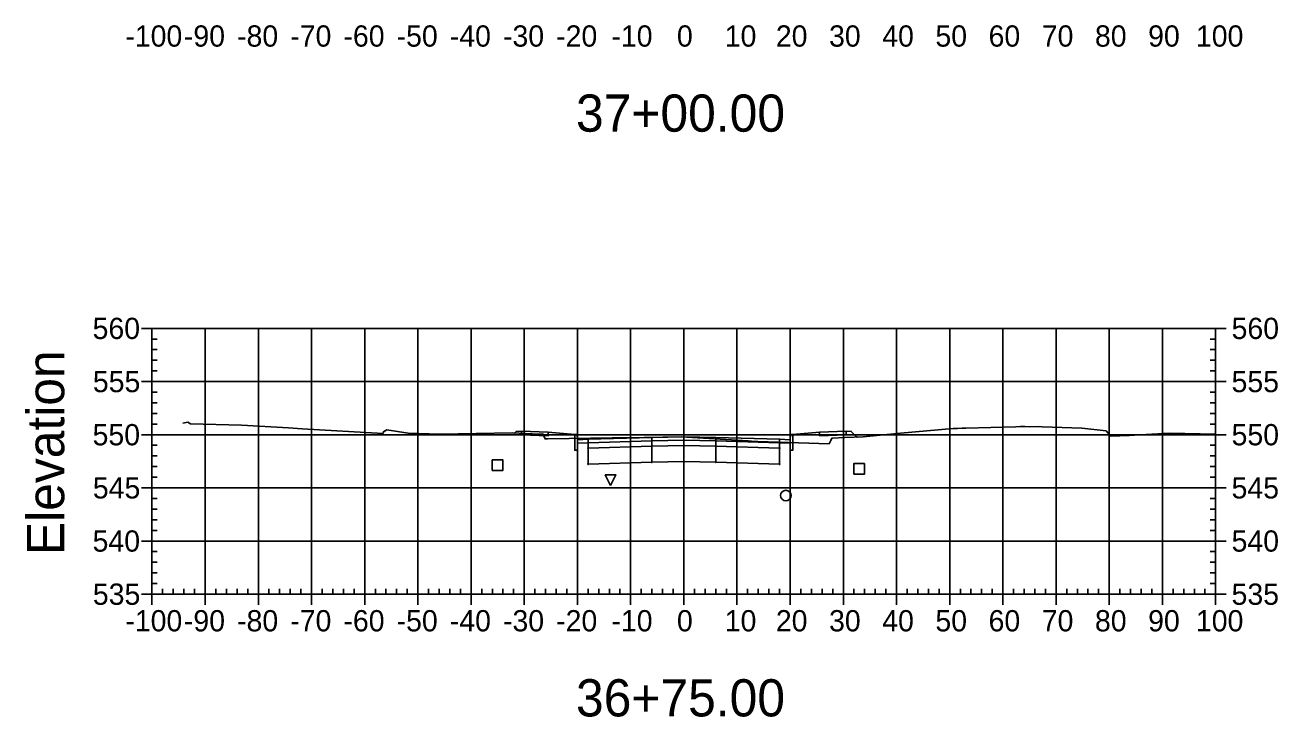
# Model space of a CAD drawing. Extents: x 704834 to 709892, y 372981 to 377533.
# Drawn here: x 709381 to 709616.6, y 376017.7 to 376147.9 of the extents above; entities that cross this region are included whole.
import ezdxf

# ---------------------------------------------------------------- set-up
doc = ezdxf.new("R2010")
doc.units = 0
for name, color, linetype in [('1', 7, 'Continuous'), ('10', 7, 'Continuous'), ('13', 7, 'Continuous'), ('14', 7, 'Continuous'), ('4', 7, 'Continuous'), ('57', 7, 'Continuous'), ('60', 7, 'Continuous'), ('Default_Xsect', 7, 'Continuous'), ('Existing', 7, 'Continuous')]:
    doc.layers.add(name, color=color, linetype=linetype)

msp = doc.modelspace()

# ---------------------------------------------------------------- linework, layer by layer
for points in [[(709473.41, 376071.44), (709473.1, 376071.12)], [(709474.41, 376071.48), (709473.41, 376071.44)], [(709484.41, 376070.88), (709479.41, 376071.28)], [(709525.41, 376070.88), (709530.41, 376071.28)], [(709535.41, 376071.48), (709536.41, 376071.44)], [(709536.41, 376071.44), (709537.47, 376070.38)]]:
    msp.add_lwpolyline(points)
for points in [[(709479.41, 376071.28), (709474.41, 376071.48), (709474.41, 376070.81), (709479.41, 376070.61)], [(709484.91, 376069.88), (709484.83, 376070.88), (709484.41, 376070.88), (709484.41, 376067.88), (709484.91, 376067.88)], [(709486.91, 376069.96), (709484.91, 376069.88), (709484.91, 376069.21), (709486.91, 376069.29)], [(709498.91, 376070.32), (709486.91, 376069.96), (709486.91, 376069.29), (709498.91, 376069.65)], [(709498.91, 376069.65), (709486.91, 376069.29), (709486.91, 376068.29), (709498.91, 376068.65)], [(709498.86, 376069.6), (709498.96, 376069.6), (709498.96, 376069.7), (709498.86, 376069.7)], [(709504.91, 376070.44), (709498.91, 376070.32), (709498.91, 376069.65), (709504.91, 376069.77)], [(709504.91, 376069.77), (709498.91, 376069.65), (709498.91, 376068.65), (709504.91, 376068.77)], [(709504.86, 376069.72), (709504.96, 376069.72), (709504.96, 376069.82), (709504.86, 376069.82)], [(709504.91, 376069.77), (709510.91, 376069.65), (709510.91, 376070.32), (709504.91, 376070.44)], [(709504.91, 376068.77), (709510.91, 376068.65), (709510.91, 376069.65), (709504.91, 376069.77)], [(709510.86, 376069.6), (709510.96, 376069.6), (709510.96, 376069.7), (709510.86, 376069.7)], [(709510.91, 376069.65), (709522.91, 376069.29), (709522.91, 376069.96), (709510.91, 376070.32)], [(709510.91, 376068.65), (709522.91, 376068.29), (709522.91, 376069.29), (709510.91, 376069.65)], [(709522.91, 376069.29), (709524.91, 376069.21), (709524.91, 376069.88), (709522.91, 376069.96)], [(709524.91, 376067.88), (709525.41, 376067.88), (709525.41, 376070.88), (709525, 376070.88), (709524.91, 376069.88)], [(709530.41, 376070.61), (709535.41, 376070.81), (709535.41, 376071.48), (709530.41, 376071.28)], [(709486.86, 376068.24), (709486.96, 376068.24), (709486.96, 376068.34), (709486.86, 376068.34)], [(709498.91, 376068.65), (709486.91, 376068.29), (709486.91, 376065.29), (709498.91, 376065.65)], [(709498.86, 376068.6), (709498.96, 376068.6), (709498.96, 376068.7), (709498.86, 376068.7)], [(709504.91, 376068.77), (709498.91, 376068.65), (709498.91, 376065.65), (709504.91, 376065.77)], [(709504.86, 376068.72), (709504.96, 376068.72), (709504.96, 376068.82), (709504.86, 376068.82)], [(709504.91, 376065.77), (709510.91, 376065.65), (709510.91, 376068.65), (709504.91, 376068.77)], [(709510.86, 376068.6), (709510.96, 376068.6), (709510.96, 376068.7), (709510.86, 376068.7)], [(709510.91, 376065.65), (709522.91, 376065.29), (709522.91, 376068.29), (709510.91, 376068.65)], [(709522.86, 376068.24), (709522.96, 376068.24), (709522.96, 376068.34), (709522.86, 376068.34)], [(709486.86, 376065.24), (709486.96, 376065.24), (709486.96, 376065.34), (709486.86, 376065.34)], [(709498.86, 376065.6), (709498.96, 376065.6), (709498.96, 376065.7), (709498.86, 376065.7)], [(709504.86, 376065.72), (709504.96, 376065.72), (709504.96, 376065.82), (709504.86, 376065.82)], [(709510.86, 376065.6), (709510.96, 376065.6), (709510.96, 376065.7), (709510.86, 376065.7)], [(709522.86, 376065.24), (709522.96, 376065.24), (709522.96, 376065.34), (709522.86, 376065.34)]]:
    msp.add_lwpolyline(points, close=True)
at = {"layer": '1'}
msp.add_lwpolyline([(709491.13, 376061.24), (709490.13, 376063.24), (709492.13, 376063.24)], close=True, dxfattribs=at)
at = {"layer": '10'}
msp.add_lwpolyline([(709468.89, 376064.09), (709470.89, 376064.09), (709470.89, 376066.09), (709468.89, 376066.09)], close=True, dxfattribs=at)
at = {"layer": '13'}
msp.add_circle((709524.1, 376059.37), 1, dxfattribs=at)
at = {"layer": '14'}
for points in [[(709473.1, 376071.12), (709473.1, 376071.17), (709473.1, 376071.12), (709473.05, 376071.12), (709473.1, 376071.12), (709473.1, 376071.07), (709473.1, 376071.12), (709473.15, 376071.12)], [(709486.91, 376069.96), (709486.91, 376070.01), (709486.91, 376069.96), (709486.86, 376069.96), (709486.91, 376069.96), (709486.91, 376069.91), (709486.91, 376069.96), (709486.96, 376069.96)], [(709504.91, 376070.44), (709504.91, 376070.49), (709504.91, 376070.44), (709504.86, 376070.44), (709504.91, 376070.44), (709504.91, 376070.39), (709504.91, 376070.44), (709504.96, 376070.44)], [(709522.91, 376069.96), (709522.91, 376070.01), (709522.91, 376069.96), (709522.86, 376069.96), (709522.91, 376069.96), (709522.91, 376069.91), (709522.91, 376069.96), (709522.96, 376069.96)], [(709537.47, 376070.38), (709537.47, 376070.43), (709537.47, 376070.38), (709537.42, 376070.38), (709537.47, 376070.38), (709537.47, 376070.33), (709537.47, 376070.38), (709537.52, 376070.38)]]:
    msp.add_lwpolyline(points, dxfattribs=at)
at = {"layer": '4'}
msp.add_lwpolyline([(709536.88, 376063.39), (709538.88, 376063.39), (709538.88, 376065.39), (709536.88, 376065.39)], close=True, dxfattribs=at)
at = {"layer": '57'}
for p, q in [((709402.91, 376090.82), (709404.91, 376090.82)), ((709404.91, 376090.82), (709604.91, 376090.82)), ((709404.91, 376040.82), (709404.91, 376090.82)), ((709404.91, 376040.82), (709404.91, 376090.82)), ((709414.91, 376040.82), (709414.91, 376090.82)), ((709424.91, 376040.82), (709424.91, 376090.82)), ((709434.91, 376040.82), (709434.91, 376090.82)), ((709444.91, 376040.82), (709444.91, 376090.82)), ((709454.91, 376040.82), (709454.91, 376090.82)), ((709464.91, 376040.82), (709464.91, 376090.82)), ((709474.91, 376040.82), (709474.91, 376090.82)), ((709484.91, 376040.82), (709484.91, 376090.82)), ((709494.91, 376040.82), (709494.91, 376090.82)), ((709504.91, 376040.82), (709504.91, 376090.82)), ((709514.91, 376040.82), (709514.91, 376090.82)), ((709524.91, 376040.82), (709524.91, 376090.82)), ((709534.91, 376040.82), (709534.91, 376090.82)), ((709544.91, 376040.82), (709544.91, 376090.82)), ((709554.91, 376040.82), (709554.91, 376090.82)), ((709564.91, 376040.82), (709564.91, 376090.82)), ((709574.91, 376040.82), (709574.91, 376090.82)), ((709584.91, 376040.82), (709584.91, 376090.82)), ((709594.91, 376040.82), (709594.91, 376090.82)), ((709604.91, 376040.82), (709604.91, 376090.82)), ((709604.91, 376040.82), (709604.91, 376090.82)), ((709606.91, 376090.82), (709604.91, 376090.82)), ((709404.91, 376088.82), (709405.91, 376088.82)), ((709604.91, 376088.82), (709603.91, 376088.82)), ((709404.91, 376086.82), (709405.91, 376086.82)), ((709604.91, 376086.82), (709603.91, 376086.82)), ((709404.91, 376084.82), (709405.91, 376084.82)), ((709604.91, 376084.82), (709603.91, 376084.82)), ((709404.91, 376082.82), (709405.91, 376082.82)), ((709604.91, 376082.82), (709603.91, 376082.82)), ((709402.91, 376080.82), (709404.91, 376080.82)), ((709404.91, 376080.82), (709604.91, 376080.82)), ((709404.91, 376078.82), (709405.91, 376078.82)), ((709604.91, 376078.82), (709603.91, 376078.82)), ((709606.91, 376080.82), (709604.91, 376080.82)), ((709404.91, 376076.82), (709405.91, 376076.82)), ((709604.91, 376076.82), (709603.91, 376076.82)), ((709404.91, 376074.82), (709405.91, 376074.82)), ((709604.91, 376074.82), (709603.91, 376074.82)), ((709404.91, 376072.82), (709405.91, 376072.82)), ((709604.91, 376072.82), (709603.91, 376072.82)), ((709402.91, 376070.82), (709404.91, 376070.82)), ((709404.91, 376070.82), (709604.91, 376070.82)), ((709606.91, 376070.82), (709604.91, 376070.82)), ((709404.91, 376068.82), (709405.91, 376068.82)), ((709604.91, 376068.82), (709603.91, 376068.82)), ((709404.91, 376066.82), (709405.91, 376066.82)), ((709404.91, 376064.82), (709405.91, 376064.82)), ((709604.91, 376066.82), (709603.91, 376066.82)), ((709604.91, 376064.82), (709603.91, 376064.82)), ((709404.91, 376062.82), (709405.91, 376062.82)), ((709604.91, 376062.82), (709603.91, 376062.82)), ((709402.91, 376060.82), (709404.91, 376060.82)), ((709404.91, 376060.82), (709604.91, 376060.82)), ((709606.91, 376060.82), (709604.91, 376060.82)), ((709404.91, 376058.82), (709405.91, 376058.82)), ((709604.91, 376058.82), (709603.91, 376058.82)), ((709404.91, 376056.82), (709405.91, 376056.82)), ((709604.91, 376056.82), (709603.91, 376056.82)), ((709404.91, 376054.82), (709405.91, 376054.82)), ((709604.91, 376054.82), (709603.91, 376054.82)), ((709402.91, 376050.82), (709404.91, 376050.82)), ((709404.91, 376052.82), (709405.91, 376052.82)), ((709404.91, 376050.82), (709604.91, 376050.82)), ((709604.91, 376052.82), (709603.91, 376052.82)), ((709606.91, 376050.82), (709604.91, 376050.82)), ((709404.91, 376048.82), (709405.91, 376048.82)), ((709604.91, 376048.82), (709603.91, 376048.82)), ((709404.91, 376046.82), (709405.91, 376046.82)), ((709604.91, 376046.82), (709603.91, 376046.82)), ((709404.91, 376044.82), (709405.91, 376044.82)), ((709604.91, 376044.82), (709603.91, 376044.82)), ((709404.91, 376042.82), (709405.91, 376042.82)), ((709406.91, 376040.82), (709406.91, 376041.82)), ((709408.91, 376040.82), (709408.91, 376041.82)), ((709410.91, 376040.82), (709410.91, 376041.82)), ((709412.91, 376040.82), (709412.91, 376041.82)), ((709416.91, 376040.82), (709416.91, 376041.82)), ((709418.91, 376040.82), (709418.91, 376041.82)), ((709420.91, 376040.82), (709420.91, 376041.82)), ((709422.91, 376040.82), (709422.91, 376041.82)), ((709426.91, 376040.82), (709426.91, 376041.82)), ((709428.91, 376040.82), (709428.91, 376041.82)), ((709430.91, 376040.82), (709430.91, 376041.82)), ((709432.91, 376040.82), (709432.91, 376041.82)), ((709436.91, 376040.82), (709436.91, 376041.82)), ((709438.91, 376040.82), (709438.91, 376041.82)), ((709440.91, 376040.82), (709440.91, 376041.82)), ((709442.91, 376040.82), (709442.91, 376041.82)), ((709446.91, 376040.82), (709446.91, 376041.82)), ((709448.91, 376040.82), (709448.91, 376041.82)), ((709450.91, 376040.82), (709450.91, 376041.82)), ((709452.91, 376040.82), (709452.91, 376041.82)), ((709456.91, 376040.82), (709456.91, 376041.82)), ((709458.91, 376040.82), (709458.91, 376041.82)), ((709460.91, 376040.82), (709460.91, 376041.82)), ((709462.91, 376040.82), (709462.91, 376041.82)), ((709466.91, 376040.82), (709466.91, 376041.82)), ((709468.91, 376040.82), (709468.91, 376041.82)), ((709470.91, 376040.82), (709470.91, 376041.82)), ((709472.91, 376040.82), (709472.91, 376041.82)), ((709476.91, 376040.82), (709476.91, 376041.82)), ((709478.91, 376040.82), (709478.91, 376041.82)), ((709480.91, 376040.82), (709480.91, 376041.82)), ((709482.91, 376040.82), (709482.91, 376041.82)), ((709486.91, 376040.82), (709486.91, 376041.82)), ((709488.91, 376040.82), (709488.91, 376041.82)), ((709490.91, 376040.82), (709490.91, 376041.82)), ((709492.91, 376040.82), (709492.91, 376041.82)), ((709496.91, 376040.82), (709496.91, 376041.82)), ((709498.91, 376040.82), (709498.91, 376041.82)), ((709500.91, 376040.82), (709500.91, 376041.82)), ((709502.91, 376040.82), (709502.91, 376041.82)), ((709506.91, 376040.82), (709506.91, 376041.82)), ((709508.91, 376040.82), (709508.91, 376041.82)), ((709510.91, 376040.82), (709510.91, 376041.82)), ((709512.91, 376040.82), (709512.91, 376041.82)), ((709516.91, 376040.82), (709516.91, 376041.82)), ((709518.91, 376040.82), (709518.91, 376041.82)), ((709520.91, 376040.82), (709520.91, 376041.82)), ((709522.91, 376040.82), (709522.91, 376041.82)), ((709526.91, 376040.82), (709526.91, 376041.82)), ((709528.91, 376040.82), (709528.91, 376041.82)), ((709530.91, 376040.82), (709530.91, 376041.82)), ((709532.91, 376040.82), (709532.91, 376041.82)), ((709536.91, 376040.82), (709536.91, 376041.82)), ((709538.91, 376040.82), (709538.91, 376041.82)), ((709540.91, 376040.82), (709540.91, 376041.82)), ((709542.91, 376040.82), (709542.91, 376041.82)), ((709546.91, 376040.82), (709546.91, 376041.82)), ((709548.91, 376040.82), (709548.91, 376041.82)), ((709550.91, 376040.82), (709550.91, 376041.82)), ((709552.91, 376040.82), (709552.91, 376041.82)), ((709556.91, 376040.82), (709556.91, 376041.82)), ((709558.91, 376040.82), (709558.91, 376041.82)), ((709560.91, 376040.82), (709560.91, 376041.82)), ((709562.91, 376040.82), (709562.91, 376041.82)), ((709566.91, 376040.82), (709566.91, 376041.82)), ((709568.91, 376040.82), (709568.91, 376041.82)), ((709570.91, 376040.82), (709570.91, 376041.82)), ((709572.91, 376040.82), (709572.91, 376041.82)), ((709576.91, 376040.82), (709576.91, 376041.82)), ((709578.91, 376040.82), (709578.91, 376041.82)), ((709580.91, 376040.82), (709580.91, 376041.82)), ((709582.91, 376040.82), (709582.91, 376041.82)), ((709586.91, 376040.82), (709586.91, 376041.82)), ((709588.91, 376040.82), (709588.91, 376041.82)), ((709590.91, 376040.82), (709590.91, 376041.82)), ((709592.91, 376040.82), (709592.91, 376041.82)), ((709596.91, 376040.82), (709596.91, 376041.82)), ((709598.91, 376040.82), (709598.91, 376041.82)), ((709600.91, 376040.82), (709600.91, 376041.82)), ((709602.91, 376040.82), (709602.91, 376041.82)), ((709604.91, 376042.82), (709603.91, 376042.82)), ((709402.91, 376040.82), (709404.91, 376040.82)), ((709404.91, 376040.82), (709604.91, 376040.82)), ((709404.91, 376040.82), (709604.91, 376040.82)), ((709404.91, 376038.82), (709404.91, 376040.82)), ((709414.91, 376038.82), (709414.91, 376040.82)), ((709424.91, 376038.82), (709424.91, 376040.82)), ((709434.91, 376038.82), (709434.91, 376040.82)), ((709444.91, 376038.82), (709444.91, 376040.82)), ((709454.91, 376038.82), (709454.91, 376040.82)), ((709464.91, 376038.82), (709464.91, 376040.82)), ((709474.91, 376038.82), (709474.91, 376040.82)), ((709484.91, 376038.82), (709484.91, 376040.82)), ((709494.91, 376038.82), (709494.91, 376040.82)), ((709504.91, 376038.82), (709504.91, 376040.82)), ((709514.91, 376038.82), (709514.91, 376040.82)), ((709524.91, 376038.82), (709524.91, 376040.82)), ((709534.91, 376038.82), (709534.91, 376040.82)), ((709544.91, 376038.82), (709544.91, 376040.82)), ((709554.91, 376038.82), (709554.91, 376040.82)), ((709564.91, 376038.82), (709564.91, 376040.82)), ((709574.91, 376038.82), (709574.91, 376040.82)), ((709584.91, 376038.82), (709584.91, 376040.82)), ((709594.91, 376038.82), (709594.91, 376040.82)), ((709604.91, 376038.82), (709604.91, 376040.82)), ((709606.91, 376040.82), (709604.91, 376040.82))]:
    msp.add_line(p, q, dxfattribs=at)
at = {"layer": 'Default_Xsect'}
msp.add_lwpolyline([(709473.1, 376071.12), (709473.41, 376071.44), (709474.41, 376071.48), (709479.41, 376071.28), (709484.41, 376070.88), (709484.83, 376070.88), (709484.91, 376069.88), (709486.91, 376069.96), (709498.91, 376070.32), (709504.91, 376070.44), (709510.91, 376070.32), (709522.91, 376069.96), (709524.91, 376069.88), (709525, 376070.88), (709525.41, 376070.88), (709530.41, 376071.28), (709535.41, 376071.48), (709536.41, 376071.44), (709537.47, 376070.38)], dxfattribs=at)
at = {"layer": 'Existing'}
msp.add_lwpolyline([(709410.69, 376072.99), (709411.64, 376073.16), (709412.14, 376072.84), (709421.72, 376072.63), (709430.6, 376072.14), (709433.13, 376071.92), (709448.35, 376071.05), (709448.44, 376071.39), (709449.05, 376071.75), (709453.05, 376071.12), (709459.01, 376070.93), (709472.71, 376071.14), (709477.66, 376070.92), (709478.38, 376071), (709478.39, 376070.97), (709478.83, 376070.04), (709479.26, 376070.05), (709491.45, 376070.24), (709497.48, 376070.28), (709504.43, 376070.4), (709517.04, 376069.66), (709517.64, 376069.62), (709518.45, 376069.57), (709518.6, 376069.57), (709518.81, 376069.56), (709532.22, 376069.08), (709532.54, 376069.74), (709532.75, 376070.14), (709535.17, 376070.28), (709538.61, 376070.42), (709545.02, 376071.02), (709545.32, 376071.06), (709545.64, 376071.1), (709555.56, 376071.97), (709556.38, 376072.01), (709557.2, 376072.04), (709557.97, 376072.06), (709567.36, 376072.33), (709568.23, 376072.35), (709569.06, 376072.34), (709569.83, 376072.33), (709571.55, 376072.35), (709572.29, 376072.31), (709579.77, 376072.06), (709584.32, 376071.52), (709585.08, 376070.69), (709585.2, 376070.52), (709588.67, 376070.69), (709590.71, 376070.79), (709596.22, 376071.1), (709604.91, 376070.93)], dxfattribs=at)

# ---------------------------------------------------------------- texts
at = {"layer": '1'}
for s, p in [('37+00.00', (709484.64, 376127.82)), ('36+75.00', (709484.64, 376017.82))]:
    msp.add_text(s, height=7, dxfattribs=at).set_placement(p)
at = {"layer": '14'}
for p in [(709474.38, 376071.43), (709474.38, 376070.76), (709479.38, 376070.56), (709530.38, 376070.56), (709535.38, 376071.43), (709535.38, 376070.76)]:
    msp.add_text('+', height=0.1, dxfattribs=at).set_placement(p)
at = {"layer": '57'}
for s, p in [('-100', (709399.9, 376143.82)), ('-90', (709410.91, 376143.82)), ('-80', (709420.91, 376143.82)), ('-70', (709430.91, 376143.82)), ('-60', (709440.91, 376143.82)), ('-50', (709450.91, 376143.82)), ('-40', (709460.91, 376143.82)), ('-30', (709470.91, 376143.82)), ('-20', (709480.91, 376143.82)), ('-10', (709491.3, 376143.82)), ('0', (709503.62, 376143.82)), ('10', (709512.61, 376143.82)), ('20', (709522.22, 376143.82)), ('30', (709532.22, 376143.82)), ('40', (709542.22, 376143.82)), ('50', (709552.22, 376143.82)), ('60', (709562.22, 376143.82)), ('70', (709572.22, 376143.82)), ('80', (709582.22, 376143.82)), ('90', (709592.22, 376143.82)), ('100', (709601.21, 376143.82)), ('560', (709393.74, 376088.82)), ('560', (709607.91, 376088.82)), ('555', (709393.79, 376078.82)), ('555', (709607.91, 376078.82)), ('550', (709393.74, 376068.82)), ('550', (709607.91, 376068.82)), ('545', (709393.79, 376058.82)), ('545', (709607.91, 376058.82)), ('540', (709393.74, 376048.82)), ('540', (709607.91, 376048.82)), ('535', (709393.79, 376038.82)), ('535', (709607.91, 376038.82)), ('-100', (709399.9, 376033.82)), ('-90', (709410.91, 376033.82)), ('-80', (709420.91, 376033.82)), ('-70', (709430.91, 376033.82)), ('-60', (709440.91, 376033.82)), ('-50', (709450.91, 376033.82)), ('-40', (709460.91, 376033.82)), ('-30', (709470.91, 376033.82)), ('-20', (709480.91, 376033.82)), ('-10', (709491.3, 376033.82)), ('0', (709503.62, 376033.82)), ('10', (709512.61, 376033.82)), ('20', (709522.22, 376033.82)), ('30', (709532.22, 376033.82)), ('40', (709542.22, 376033.82)), ('50', (709552.22, 376033.82)), ('60', (709562.22, 376033.82)), ('70', (709572.22, 376033.82)), ('80', (709582.22, 376033.82)), ('90', (709592.22, 376033.82)), ('100', (709601.21, 376033.82))]:
    msp.add_text(s, height=4, dxfattribs=at).set_placement(p)
at = {"layer": '60'}
msp.add_text('Elevation', height=7, rotation=90, dxfattribs=at).set_placement((709388.41, 376048.18))

doc.saveas('drawing.dxf')
